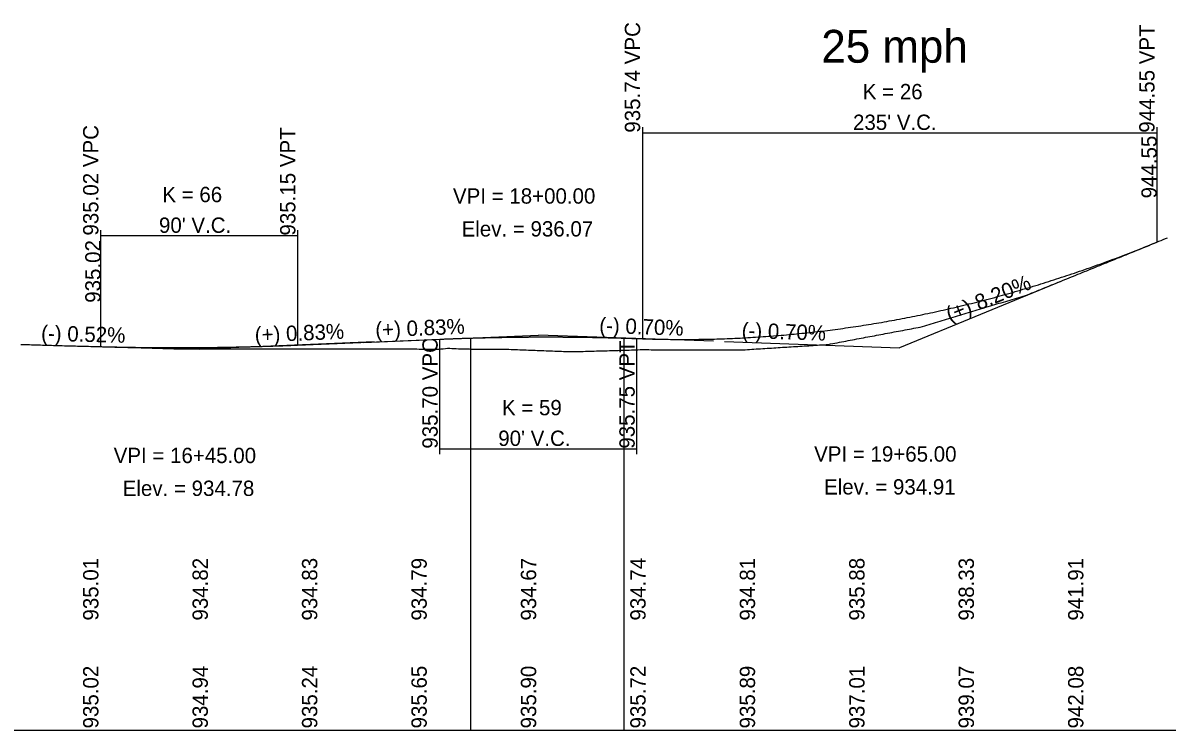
# Model space of a CAD drawing. Extents: x 1573485 to 1576468, y 1104256 to 1106756.
# Drawn here: x 1575320 to 1575843, y 1105506 to 1105829 of the extents above; entities that cross this region are included whole.
import ezdxf

# ---------------------------------------------------------------- set-up
doc = ezdxf.new("R2010")
doc.units = 0
for name, color, linetype in [('Default', 7, 'Continuous'), ('RD_DDB_GradeTX', 7, 'Continuous'), ('RD_DDB_Profile_EX', 7, 'Continuous'), ('RD_DDB_Profile_Lbl', 7, 'Continuous'), ('RD_DDB_Profile_PR', 7, 'Continuous'), ('RD_DDB_StripGrade', 7, 'Continuous'), ('RD_DDB_VCLbl', 7, 'Continuous'), ('RD_GPK_Profile_Cell', 7, 'Continuous'), ('RD_PD_Bridge', 7, 'Continuous')]:
    doc.layers.add(name, color=color, linetype=linetype)

msp = doc.modelspace()

# ---------------------------------------------------------------- linework, layer by layer
at = {"layer": 'RD_DDB_GradeTX'}
for p, q in [((1575795.02, 1105711), (1575721, 1105680.64)), ((1575476.07, 1105683.1), (1575556, 1105686.43)), ((1575635.95, 1105683.62), (1575556, 1105686.43)), ((1575356, 1105681.16), (1575401, 1105679.98)), ((1575480.93, 1105683.31), (1575401, 1105679.98)), ((1575641.05, 1105683.45), (1575721, 1105680.64))]:
    msp.add_line(p, q, dxfattribs=at)
at = {"layer": 'RD_DDB_Profile_EX'}
for points in [[(1575777.5, 1105704.24), (1575778.5, 1105704.55), (1575779.5, 1105704.85), (1575780.5, 1105705.26), (1575781.5, 1105705.66), (1575782.5, 1105706.07), (1575783.5, 1105706.47), (1575784.5, 1105706.88), (1575785.5, 1105707.29), (1575786.5, 1105707.69), (1575787.5, 1105708.1), (1575788.5, 1105708.5), (1575789.5, 1105708.91), (1575790.5, 1105709.31), (1575791.5, 1105709.72), (1575792.5, 1105710.13), (1575793.5, 1105710.53), (1575794.5, 1105710.94), (1575795.5, 1105711.34), (1575796.5, 1105711.75), (1575797.5, 1105712.16), (1575798.5, 1105712.56), (1575799.5, 1105712.97), (1575800.5, 1105713.37), (1575801.5, 1105713.78), (1575802.5, 1105714.19), (1575803.5, 1105714.59), (1575804.5, 1105715), (1575805.5, 1105715.41), (1575806.5, 1105715.81), (1575807.5, 1105716.22), (1575808.5, 1105716.62), (1575809.5, 1105717.03), (1575810.5, 1105717.44), (1575811.5, 1105717.84), (1575812.5, 1105718.25), (1575813.5, 1105718.66), (1575814.5, 1105719.06), (1575815.5, 1105719.47), (1575816.5, 1105719.88), (1575817.5, 1105720.28), (1575818.5, 1105720.69), (1575819.5, 1105721.1), (1575820.5, 1105721.5), (1575821.5, 1105721.91), (1575822.5, 1105722.32), (1575823.5, 1105722.72), (1575824.5, 1105723.13), (1575825.5, 1105723.54), (1575826.5, 1105723.94), (1575827.5, 1105724.35), (1575828.5, 1105724.76), (1575829.5, 1105725.16), (1575830.5, 1105725.57), (1575831.5, 1105725.98), (1575832.5, 1105726.39), (1575833.5, 1105726.79), (1575834.5, 1105727.2), (1575835.5, 1105727.61), (1575836.5, 1105728.01), (1575837.5, 1105728.42), (1575838.5, 1105728.83), (1575839.5, 1105729.23), (1575840.5, 1105729.64), (1575841.5, 1105730.05), (1575842.5, 1105730.46), (1575843.5, 1105730.86)], [(1575677.5, 1105681.46), (1575678.5, 1105681.52), (1575679.5, 1105681.59), (1575680.5, 1105681.65), (1575681.5, 1105681.71), (1575682.5, 1105681.77), (1575683.5, 1105681.83), (1575684.5, 1105681.9), (1575685.5, 1105681.96), (1575686.5, 1105682.02), (1575687.5, 1105682.08), (1575688.5, 1105682.18), (1575689.5, 1105682.39), (1575690.5, 1105682.58), (1575691.5, 1105682.77), (1575692.5, 1105682.96), (1575693.5, 1105683.15), (1575694.5, 1105683.33), (1575695.5, 1105683.52), (1575696.5, 1105683.71), (1575697.5, 1105683.9), (1575698.5, 1105684.08), (1575699.5, 1105684.27), (1575700.5, 1105684.46), (1575701.5, 1105684.65), (1575702.5, 1105684.84), (1575703.5, 1105685.02), (1575704.5, 1105685.21), (1575705.5, 1105685.4), (1575706.5, 1105685.59), (1575707.5, 1105685.77), (1575708.5, 1105685.96), (1575709.5, 1105686.15), (1575710.5, 1105686.34), (1575711.5, 1105686.52), (1575712.5, 1105686.71), (1575713.5, 1105686.9), (1575714.5, 1105687.09), (1575715.5, 1105687.27), (1575716.5, 1105687.46), (1575717.5, 1105687.65), (1575718.5, 1105687.84), (1575719.5, 1105688.02), (1575720.5, 1105688.21), (1575721.5, 1105688.4), (1575722.5, 1105688.58), (1575723.5, 1105688.77), (1575724.5, 1105688.95), (1575725.5, 1105689.14), (1575726.5, 1105689.33), (1575727.5, 1105689.51), (1575728.5, 1105689.7), (1575729.5, 1105689.89), (1575730.5, 1105690.08), (1575731.5, 1105690.38), (1575732.5, 1105690.68), (1575733.5, 1105690.98), (1575734.5, 1105691.28), (1575735.5, 1105691.58), (1575736.5, 1105691.88), (1575737.5, 1105692.18), (1575738.5, 1105692.48), (1575739.5, 1105692.78), (1575740.5, 1105693.08), (1575741.5, 1105693.38), (1575742.5, 1105693.69), (1575743.5, 1105693.99), (1575744.5, 1105694.29), (1575745.5, 1105694.59), (1575746.5, 1105694.89), (1575747.5, 1105695.19), (1575748.5, 1105695.49), (1575749.5, 1105695.79), (1575750.5, 1105696.09), (1575751.5, 1105696.4), (1575752.5, 1105696.7), (1575753.5, 1105697), (1575754.5, 1105697.3), (1575755.5, 1105697.6), (1575756.5, 1105697.9), (1575757.5, 1105698.2), (1575758.5, 1105698.51), (1575759.5, 1105698.81), (1575760.5, 1105699.11), (1575761.5, 1105699.41), (1575762.5, 1105699.71), (1575763.5, 1105700.02), (1575764.5, 1105700.32), (1575765.5, 1105700.62), (1575766.5, 1105700.92), (1575767.5, 1105701.22), (1575768.5, 1105701.52), (1575769.5, 1105701.83), (1575770.5, 1105702.13), (1575771.5, 1105702.43), (1575772.5, 1105702.73), (1575773.5, 1105703.03), (1575774.5, 1105703.34), (1575775.5, 1105703.64), (1575776.5, 1105703.94), (1575777.5, 1105704.24)], [(1575319.5, 1105682.17), (1575320.5, 1105682.14), (1575321.5, 1105682.11), (1575322.5, 1105682.08), (1575323.5, 1105682.05), (1575324.5, 1105682.02), (1575325.5, 1105681.99), (1575326.5, 1105681.96), (1575327.5, 1105681.93), (1575328.5, 1105681.9), (1575329.5, 1105681.87), (1575330.5, 1105681.84), (1575331.5, 1105681.81), (1575332.5, 1105681.78), (1575333.5, 1105681.75), (1575334.5, 1105681.72), (1575335.5, 1105681.69), (1575336.5, 1105681.66), (1575337.5, 1105681.63), (1575338.5, 1105681.6), (1575339.5, 1105681.57), (1575340.5, 1105681.55), (1575341.5, 1105681.53), (1575342.5, 1105681.5), (1575343.5, 1105681.48), (1575344.5, 1105681.45), (1575345.5, 1105681.42), (1575346.5, 1105681.4), (1575347.5, 1105681.37), (1575348.5, 1105681.35), (1575349.5, 1105681.32), (1575350.5, 1105681.3), (1575351.5, 1105681.27), (1575352.5, 1105681.25), (1575353.5, 1105681.22), (1575354.5, 1105681.19), (1575355.5, 1105681.17), (1575356.5, 1105681.14), (1575357.5, 1105681.11), (1575358.5, 1105681.09), (1575359.5, 1105681.06), (1575360.5, 1105681.03), (1575361.5, 1105681.01), (1575362.5, 1105680.98), (1575363.5, 1105680.95), (1575364.5, 1105680.93), (1575365.5, 1105680.9), (1575366.5, 1105680.87), (1575367.5, 1105680.85), (1575368.5, 1105680.82), (1575369.5, 1105680.79), (1575370.5, 1105680.76), (1575371.5, 1105680.74), (1575372.5, 1105680.71), (1575373.5, 1105680.68), (1575374.5, 1105680.65), (1575375.5, 1105680.62), (1575376.5, 1105680.59), (1575377.5, 1105680.57)], [(1575377.5, 1105680.57), (1575378.5, 1105680.54), (1575379.5, 1105680.51), (1575380.5, 1105680.48), (1575381.5, 1105680.45), (1575382.5, 1105680.42), (1575383.5, 1105680.39), (1575384.5, 1105680.37), (1575385.5, 1105680.34), (1575386.5, 1105680.31), (1575387.5, 1105680.28), (1575388.5, 1105680.25), (1575389.5, 1105680.22), (1575390.5, 1105680.19), (1575391.5, 1105680.16), (1575392.5, 1105680.13), (1575393.5, 1105680.1), (1575394.5, 1105680.12), (1575395.5, 1105680.13), (1575396.5, 1105680.13), (1575397.5, 1105680.13), (1575398.5, 1105680.14), (1575399.5, 1105680.14), (1575400.5, 1105680.14), (1575401.5, 1105680.14), (1575402.5, 1105680.15), (1575403.5, 1105680.15), (1575404.5, 1105680.15), (1575405.5, 1105680.15), (1575406.5, 1105680.16), (1575407.5, 1105680.16), (1575408.5, 1105680.16), (1575409.5, 1105680.16), (1575410.5, 1105680.16), (1575411.5, 1105680.17), (1575412.5, 1105680.17), (1575413.5, 1105680.17), (1575414.5, 1105680.17), (1575415.5, 1105680.17), (1575416.5, 1105680.17), (1575417.5, 1105680.18), (1575418.5, 1105680.18), (1575419.5, 1105680.18), (1575420.5, 1105680.18), (1575421.5, 1105680.18), (1575422.5, 1105680.18), (1575423.5, 1105680.18), (1575424.5, 1105680.18), (1575425.5, 1105680.19), (1575426.5, 1105680.19), (1575427.5, 1105680.19), (1575428.5, 1105680.19), (1575429.5, 1105680.19), (1575430.5, 1105680.19), (1575431.5, 1105680.19), (1575432.5, 1105680.19), (1575433.5, 1105680.19), (1575434.5, 1105680.19), (1575435.5, 1105680.19), (1575436.5, 1105680.19), (1575437.5, 1105680.19), (1575438.5, 1105680.19), (1575439.5, 1105680.19), (1575440.5, 1105680.19), (1575441.5, 1105680.19), (1575442.5, 1105680.19), (1575443.5, 1105680.19), (1575444.5, 1105680.19), (1575445.5, 1105680.19), (1575446.5, 1105680.19), (1575447.5, 1105680.2), (1575448.5, 1105680.21), (1575449.5, 1105680.21), (1575450.5, 1105680.22), (1575451.5, 1105680.22), (1575452.5, 1105680.22), (1575453.5, 1105680.21), (1575454.5, 1105680.21), (1575455.5, 1105680.21), (1575456.5, 1105680.21), (1575457.5, 1105680.21), (1575458.5, 1105680.2), (1575459.5, 1105680.2), (1575460.5, 1105680.2), (1575461.5, 1105680.2), (1575462.5, 1105680.2), (1575463.5, 1105680.19), (1575464.5, 1105680.19), (1575465.5, 1105680.19), (1575466.5, 1105680.19), (1575467.5, 1105680.18), (1575468.5, 1105680.18), (1575469.5, 1105680.18), (1575470.5, 1105680.18), (1575471.5, 1105680.17), (1575472.5, 1105680.17), (1575473.5, 1105680.17), (1575474.5, 1105680.16), (1575475.5, 1105680.16), (1575476.5, 1105680.16), (1575477.5, 1105680.15)], [(1575477.5, 1105680.15), (1575478.5, 1105680.15), (1575479.5, 1105680.15), (1575480.5, 1105680.14), (1575481.5, 1105680.14), (1575482.5, 1105680.14), (1575483.5, 1105680.13), (1575484.5, 1105680.13), (1575485.5, 1105680.13), (1575486.5, 1105680.12), (1575487.5, 1105680.12), (1575488.5, 1105680.12), (1575489.5, 1105680.11), (1575490.5, 1105680.11), (1575491.5, 1105680.11), (1575492.5, 1105680.1), (1575493.5, 1105680.1), (1575494.5, 1105680.09), (1575495.5, 1105680.09), (1575496.5, 1105680.08), (1575497.5, 1105680.08), (1575498.5, 1105680.08), (1575499.5, 1105680.07), (1575500.5, 1105680.07), (1575501.5, 1105680.06), (1575502.5, 1105680.06), (1575503.5, 1105680.05), (1575504.5, 1105680.05), (1575505.5, 1105680.04), (1575506.5, 1105680.04), (1575507.5, 1105680.04), (1575508.5, 1105680.03), (1575509.5, 1105680.03), (1575510.5, 1105680.05), (1575511.5, 1105680.13), (1575512.5, 1105680.21), (1575513.5, 1105680.3), (1575514.5, 1105680.38), (1575515.5, 1105680.41), (1575516.5, 1105680.36), (1575517.5, 1105680.31), (1575518.5, 1105680.25), (1575519.5, 1105680.2), (1575520.5, 1105680.15), (1575521.5, 1105680.1), (1575522.5, 1105680.08), (1575523.5, 1105680.07), (1575524.5, 1105680.07), (1575525.5, 1105680.06), (1575526.5, 1105680.05), (1575527.5, 1105680.05), (1575528.5, 1105680.04), (1575529.5, 1105680.03), (1575530.5, 1105680.03), (1575531.5, 1105680.02), (1575532.5, 1105680.01), (1575533.5, 1105680.01), (1575534.5, 1105680), (1575535.5, 1105679.99), (1575536.5, 1105679.99), (1575537.5, 1105679.98), (1575538.5, 1105679.97), (1575539.5, 1105679.97), (1575540.5, 1105679.96), (1575541.5, 1105679.95), (1575542.5, 1105679.95), (1575543.5, 1105679.91), (1575544.5, 1105679.87), (1575545.5, 1105679.83), (1575546.5, 1105679.8), (1575547.5, 1105679.76), (1575548.5, 1105679.72), (1575549.5, 1105679.68), (1575550.5, 1105679.64), (1575551.5, 1105679.6), (1575552.5, 1105679.56), (1575553.5, 1105679.52), (1575554.5, 1105679.49), (1575555.5, 1105679.45), (1575556.5, 1105679.41), (1575557.5, 1105679.37), (1575558.5, 1105679.33), (1575559.5, 1105679.29), (1575560.5, 1105679.25), (1575561.5, 1105679.21), (1575562.5, 1105679.17), (1575563.5, 1105679.13), (1575564.5, 1105679.09), (1575565.5, 1105679.05), (1575566.5, 1105679.01), (1575567.5, 1105678.98), (1575568.5, 1105678.96), (1575569.5, 1105678.94), (1575570.5, 1105678.91), (1575571.5, 1105678.89), (1575572.5, 1105678.86), (1575573.5, 1105678.89), (1575574.5, 1105678.92), (1575575.5, 1105678.95), (1575576.5, 1105678.98), (1575577.5, 1105679.01)], [(1575577.5, 1105679.01), (1575578.5, 1105679.04), (1575579.5, 1105679.07), (1575580.5, 1105679.1), (1575581.5, 1105679.13), (1575582.5, 1105679.16), (1575583.5, 1105679.19), (1575584.5, 1105679.22), (1575585.5, 1105679.24), (1575586.5, 1105679.27), (1575587.5, 1105679.3), (1575588.5, 1105679.33), (1575589.5, 1105679.36), (1575590.5, 1105679.39), (1575591.5, 1105679.42), (1575592.5, 1105679.45), (1575593.5, 1105679.48), (1575594.5, 1105679.51), (1575595.5, 1105679.53), (1575596.5, 1105679.56), (1575597.5, 1105679.59), (1575598.5, 1105679.63), (1575599.5, 1105679.66), (1575600.5, 1105679.7), (1575601.5, 1105679.74), (1575602.5, 1105679.78), (1575603.5, 1105679.78), (1575604.5, 1105679.78), (1575605.5, 1105679.77), (1575606.5, 1105679.77), (1575607.5, 1105679.76), (1575608.5, 1105679.76), (1575609.5, 1105679.76), (1575610.5, 1105679.75), (1575611.5, 1105679.75), (1575612.5, 1105679.75), (1575613.5, 1105679.74), (1575614.5, 1105679.74), (1575615.5, 1105679.73), (1575616.5, 1105679.73), (1575617.5, 1105679.73), (1575618.5, 1105679.72), (1575619.5, 1105679.72), (1575620.5, 1105679.71), (1575621.5, 1105679.71), (1575622.5, 1105679.71), (1575623.5, 1105679.71), (1575624.5, 1105679.71), (1575625.5, 1105679.72), (1575626.5, 1105679.72), (1575627.5, 1105679.72), (1575628.5, 1105679.72), (1575629.5, 1105679.72), (1575630.5, 1105679.71), (1575631.5, 1105679.71), (1575632.5, 1105679.71), (1575633.5, 1105679.71), (1575634.5, 1105679.71), (1575635.5, 1105679.7), (1575636.5, 1105679.7), (1575637.5, 1105679.7), (1575638.5, 1105679.7), (1575639.5, 1105679.7), (1575640.5, 1105679.69), (1575641.5, 1105679.69), (1575642.5, 1105679.69), (1575643.5, 1105679.69), (1575644.5, 1105679.69), (1575645.5, 1105679.68), (1575646.5, 1105679.7), (1575647.5, 1105679.71), (1575648.5, 1105679.73), (1575649.5, 1105679.74), (1575650.5, 1105679.76), (1575651.5, 1105679.82), (1575652.5, 1105679.88), (1575653.5, 1105679.95), (1575654.5, 1105680.01), (1575655.5, 1105680.08), (1575656.5, 1105680.14), (1575657.5, 1105680.2), (1575658.5, 1105680.27), (1575659.5, 1105680.33), (1575660.5, 1105680.39), (1575661.5, 1105680.46), (1575662.5, 1105680.52), (1575663.5, 1105680.58), (1575664.5, 1105680.65), (1575665.5, 1105680.71), (1575666.5, 1105680.77), (1575667.5, 1105680.84), (1575668.5, 1105680.9), (1575669.5, 1105680.96), (1575670.5, 1105681.02), (1575671.5, 1105681.09), (1575672.5, 1105681.15), (1575673.5, 1105681.21), (1575674.5, 1105681.27), (1575675.5, 1105681.34), (1575676.5, 1105681.4), (1575677.5, 1105681.46)]]:
    msp.add_lwpolyline(points, dxfattribs=at)
at = {"layer": 'RD_DDB_Profile_PR'}
for p, q in [((1575446, 1105681.85), (1575511, 1105684.56)), ((1575601, 1105684.85), (1575603.5, 1105684.76))]:
    msp.add_line(p, q, dxfattribs=at)
for points in [[(1575603.5, 1105684.76), (1575608.2, 1105684.62), (1575612.9, 1105684.52), (1575617.6, 1105684.46), (1575622.3, 1105684.44), (1575627, 1105684.46), (1575631.7, 1105684.53), (1575636.4, 1105684.63), (1575641.1, 1105684.78), (1575645.8, 1105684.97), (1575650.5, 1105685.21), (1575655.2, 1105685.48), (1575659.9, 1105685.8), (1575664.6, 1105686.16), (1575669.3, 1105686.56), (1575674, 1105687), (1575678.7, 1105687.48), (1575683.4, 1105688.01), (1575688.1, 1105688.57), (1575692.8, 1105689.18), (1575697.5, 1105689.83), (1575702.2, 1105690.53), (1575706.9, 1105691.26), (1575711.6, 1105692.04), (1575716.3, 1105692.86), (1575721, 1105693.72), (1575725.7, 1105694.62), (1575730.4, 1105695.56), (1575735.1, 1105696.55), (1575739.8, 1105697.58), (1575744.5, 1105698.65), (1575749.2, 1105699.76), (1575753.9, 1105700.91), (1575758.6, 1105702.11), (1575763.3, 1105703.34), (1575768, 1105704.62), (1575772.7, 1105705.94), (1575777.4, 1105707.31), (1575782.1, 1105708.71), (1575786.8, 1105710.16), (1575791.5, 1105711.65), (1575796.2, 1105713.18), (1575800.9, 1105714.75), (1575805.6, 1105716.36), (1575810.3, 1105718.02), (1575815, 1105719.71), (1575819.7, 1105721.45), (1575824.4, 1105723.23), (1575829.1, 1105725.06), (1575833.8, 1105726.92), (1575838.5, 1105728.83)], [(1575511, 1105684.56), (1575512.8, 1105684.63), (1575514.6, 1105684.7), (1575516.4, 1105684.77), (1575518.2, 1105684.83), (1575520, 1105684.9), (1575521.8, 1105684.96), (1575523.6, 1105685.01), (1575525.4, 1105685.07), (1575527.2, 1105685.12), (1575529, 1105685.17), (1575530.8, 1105685.21), (1575532.6, 1105685.26), (1575534.4, 1105685.3), (1575536.2, 1105685.33), (1575538, 1105685.37), (1575539.8, 1105685.4), (1575541.6, 1105685.43), (1575543.4, 1105685.46), (1575545.2, 1105685.48), (1575547, 1105685.5), (1575548.8, 1105685.52), (1575550.6, 1105685.54), (1575552.4, 1105685.55), (1575554.2, 1105685.56), (1575556, 1105685.57), (1575557.8, 1105685.57), (1575559.6, 1105685.57), (1575561.4, 1105685.57), (1575563.2, 1105685.57), (1575565, 1105685.56), (1575566.8, 1105685.55), (1575568.6, 1105685.54), (1575570.4, 1105685.53), (1575572.2, 1105685.51), (1575574, 1105685.49), (1575575.8, 1105685.46), (1575577.6, 1105685.44), (1575579.4, 1105685.41), (1575581.2, 1105685.38), (1575583, 1105685.34), (1575584.8, 1105685.31), (1575586.6, 1105685.27), (1575588.4, 1105685.23), (1575590.2, 1105685.18), (1575592, 1105685.13), (1575593.8, 1105685.08), (1575595.6, 1105685.03), (1575597.4, 1105684.97), (1575599.2, 1105684.91), (1575601, 1105684.85)], [(1575356, 1105681.16), (1575357.8, 1105681.11), (1575359.6, 1105681.07), (1575361.4, 1105681.02), (1575363.2, 1105680.99), (1575365, 1105680.95), (1575366.8, 1105680.92), (1575368.6, 1105680.89), (1575370.4, 1105680.86), (1575372.2, 1105680.83), (1575374, 1105680.81), (1575375.8, 1105680.79), (1575377.6, 1105680.77), (1575379.4, 1105680.75), (1575381.2, 1105680.74), (1575383, 1105680.72), (1575384.8, 1105680.71), (1575386.6, 1105680.71), (1575388.4, 1105680.7), (1575390.2, 1105680.7), (1575392, 1105680.7), (1575393.8, 1105680.71), (1575395.6, 1105680.71), (1575397.4, 1105680.72), (1575399.2, 1105680.73), (1575401, 1105680.74), (1575402.8, 1105680.76), (1575404.6, 1105680.77), (1575406.4, 1105680.79), (1575408.2, 1105680.82), (1575410, 1105680.84), (1575411.8, 1105680.87), (1575413.6, 1105680.9), (1575415.4, 1105680.93), (1575417.2, 1105680.97), (1575419, 1105681), (1575420.8, 1105681.04), (1575422.6, 1105681.08), (1575424.4, 1105681.13), (1575426.2, 1105681.18), (1575428, 1105681.22), (1575429.8, 1105681.28), (1575431.6, 1105681.33), (1575433.4, 1105681.39), (1575435.2, 1105681.45), (1575437, 1105681.51), (1575438.8, 1105681.57), (1575440.6, 1105681.64), (1575442.4, 1105681.71), (1575444.2, 1105681.78), (1575446, 1105681.85)]]:
    msp.add_spline(points, degree=3, dxfattribs=at)
at = {"layer": 'RD_DDB_VCLbl'}
for p, q in [((1575603.5, 1105781.33), (1575603.5, 1105684.76)), ((1575838.5, 1105781.33), (1575838.5, 1105728.83)), ((1575603.5, 1105778.83), (1575838.5, 1105778.83)), ((1575356, 1105734.35), (1575356, 1105681.16)), ((1575446, 1105734.35), (1575446, 1105681.85)), ((1575356, 1105731.85), (1575446, 1105731.85)), ((1575511, 1105632.06), (1575511, 1105684.56)), ((1575601, 1105632.06), (1575601, 1105684.85)), ((1575511, 1105634.56), (1575601, 1105634.56))]:
    msp.add_line(p, q, dxfattribs=at)
at = {"layer": 'RD_GPK_Profile_Cell'}
msp.add_line((1574956, 1105506.08), (1576456, 1105506.08), dxfattribs=at)
at = {"layer": 'RD_PD_Bridge'}
for p, q in [((1575525.21, 1105506.08), (1575525.21, 1105685.06)), ((1575595.21, 1105506.08), (1575595.21, 1105684.53))]:
    msp.add_line(p, q, dxfattribs=at)

# ---------------------------------------------------------------- texts
at = {"layer": 'Default'}
msp.add_text('25 mph', height=15, dxfattribs=at).set_placement((1575685.27, 1105810.77))
at = {"layer": 'RD_DDB_GradeTX'}
for s, rotation, p in [('(+) 8.20%', 22.2987, (1575743.99, 1105692.23)), ('(-) 0.52%', 358.5035, (1575328.76, 1105683.87)), ('(+) 0.83%', 2.3829, (1575426.57, 1105683.05)), ('(+) 0.83%', 2.3829, (1575481.65, 1105685.34)), ('(-) 0.70%', 357.9907, (1575583.74, 1105687.46)), ('(-) 0.70%', 357.9907, (1575648.8, 1105685.18))]:
    msp.add_text(s, height=7, rotation=rotation, dxfattribs=at).set_placement(p)
at = {"layer": 'RD_DDB_Profile_Lbl'}
for s, p in [('944.55', (1575838.5, 1105748.83)), ('935.02', (1575356, 1105701.16))]:
    msp.add_text(s, height=7, rotation=90, dxfattribs=at).set_placement(p)
for s, p in [('VPI = 18+00.00', (1575516.98, 1105746.43)), ('Elev. = 936.07', (1575520.94, 1105731.43)), ('VPI = 16+45.00', (1575361.98, 1105627.98)), ('VPI = 19+65.00', (1575681.98, 1105628.64)), ('Elev. = 934.78', (1575366.11, 1105612.98)), ('Elev. = 934.91', (1575686.53, 1105613.64))]:
    msp.add_text(s, height=7, dxfattribs=at).set_placement(p)
at = {"layer": 'RD_DDB_StripGrade'}
for s, p in [('935.74 VPC', (1575602.5, 1105778.83)), ('944.55 VPT', (1575837.5, 1105778.83)), ('935.02 VPC', (1575355, 1105731.85)), ('935.15 VPT', (1575445, 1105731.85)), ('935.70 VPC', (1575510, 1105634.56)), ('935.75 VPT', (1575600, 1105634.56)), ('935.01', (1575355, 1105556.08)), ('934.82', (1575405, 1105556.08)), ('934.83', (1575455, 1105556.08)), ('934.79', (1575505, 1105556.08)), ('934.67', (1575555, 1105556.08)), ('934.74', (1575605, 1105556.08)), ('934.81', (1575655, 1105556.08)), ('935.88', (1575705, 1105556.08)), ('938.33', (1575755, 1105556.08)), ('941.91', (1575805, 1105556.08)), ('935.02', (1575355, 1105506.83)), ('934.94', (1575405, 1105506.83)), ('935.24', (1575455, 1105506.83)), ('935.65', (1575505, 1105506.83)), ('935.90', (1575555, 1105506.83)), ('935.72', (1575605, 1105506.83)), ('935.89', (1575655, 1105506.83)), ('937.01', (1575705, 1105506.83)), ('939.07', (1575755, 1105506.83)), ('942.08', (1575805, 1105506.83))]:
    msp.add_text(s, height=7, rotation=90, dxfattribs=at).set_placement(p)
at = {"layer": 'RD_DDB_VCLbl'}
for s, p in [('K = 26', (1575704.22, 1105794.08)), ("235' V.C.", (1575699.75, 1105780.08)), ('K = 66', (1575384.22, 1105747.1)), ("90' V.C.", (1575382.68, 1105733.1)), ('K = 59', (1575539.38, 1105649.81)), ("90' V.C.", (1575537.68, 1105635.81))]:
    msp.add_text(s, height=7, dxfattribs=at).set_placement(p)

doc.saveas('drawing.dxf')
